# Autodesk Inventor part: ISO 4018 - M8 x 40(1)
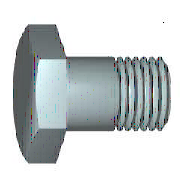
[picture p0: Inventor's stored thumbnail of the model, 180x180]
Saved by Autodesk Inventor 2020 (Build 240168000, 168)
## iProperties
Created: 2019-01
Part Number: ISO 4018 - M8 x 40(1)
Material: Ocel
Description: Šrouby se šestihrannou hlavou se závitem k hlavě. Výrobní třída C
Document SubType Name: Modeling
Standard: ISO 4018
Designer: doma
Standard Revision: Fourth edition 2011-04-01
Standards Organization: ISO
Language: cs-CZ
Size Designation: M8 x 40
Categories: <MemberInstance><Categories><Category DisplayName="Spojovací materiál" InternalName="e4da775c-781d-43d5-af7c-5136215cf5a6" Mnemonic="FSTN"><Category DisplayName
Density: 7.85 g/cm^3
Appearance: Plech
IsCustomPart: 0
Author: doma
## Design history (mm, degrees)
node "WorkPlane1"
node "WorkPoint1"
node "MSC_A1"
node "MSC_PF1"
node "MSC_PT1"
body "Solid1"
node "Náčrt1"
sketch "Náčrt2"
  geometry: L1 (-6.5, 3.753)-(-6.5, -3.753); L2 (0, 7.505)-(-6.5, 3.753); L3 (6.5, 3.753)-(0, 7.505); L4 (6.5, -3.753)-(6.5, 3.753); L5 (0, -7.505)-(6.5, -3.753); L6 (-6.5, -3.753)-(0, -7.505); C1 r 6.5 at (0, 0); 1 further point
  constraints: 12 end point, 6 tangent, 2 parallel, 2 vertical, 1 centre point
  dimensions: "d1" = 13 diameter of C1 (= ParS); "d29" = 0 distance of point (0, 0) C1.centre; "d30" = 0 distance of C1.centre point (0, 0)
extrude "Vysunutí1" new body sketch "Náčrt2" distance "d6" = 5.3 (= ParK); taper "d7" = 0 deg
revolve "Rotace1" stored, may be unused: angle "d14" = 360 deg
revolve "Rotace2" stored, may be unused: angle "d21" = 360 deg
chamfer "Zkosení1" distance "d22" = 0.625 (= 0.5 x PTC); stored, may be unused: second distance "d23" = 0.625 (= 0.5 x PTC), angle "d39" = 45 deg
fillet "Zaoblení1" dims "d24" = 0.4 (= r)
feature "Závit1" dims "d32" = 0, "b" = 37.5 (= NLG - 2 x PTC)
sketch "Náčrt3"
  geometry: L1 (6.5, 5.3)-(7.605, 5.3); L2 (7.605, 4.662)-(6.5, 5.3); L3 (7.605, 5.3)-(7.605, 4.662); L4 (0, -1.06)-(0, 6.36) reference; L5 (7.505, 0)-(7.505, 5.3) reference
  constraints: 6 end point, 1 horizontal, 1 vertical
  dimensions: "d25" = 0.1 distance between parallel lines of L5 L3; "d26" = 0 distance from line of L5.end L1; "d27" = 60 deg angle of L3 L2; "d28" = 6.5 distance from line of L4 L1.start (= 0.5 x ParS)
sketch "Náčrt4"
  geometry: L1 (0, -40)-(0, 0); L2 (-4, -40)-(0, -40); L3 (-4, 0)-(-4, -40); L4 (0, 0)-(-4, 0); L5 (0, -40)-(0, 0); L6 (-4.8, 0)-(0.8, 0) reference; L7 (0, -48)-(0, 8) reference
  constraints: 10 end point, 2 horizontal, 2 vertical
  dimensions: "d18" = 4 distance of L1.start L2.start (= 0.5 x NND); "d20" = 40 distance of L3.start L2.start (= NLG); "d33" = 0 distance between parallel lines of L7 L1; "d34" = 0 distance between parallel lines of L6 L4
other parameters: "NND" = 8 [user parameter; used in 2 equation terms], "NLG" = 40 [user parameter; used in 2 equation terms], "PTC" = 1.25 [user parameter; used in 3 equation terms], "ParK" = 5.3 [user parameter; used in 1 equation term], "ParS" = 13 [user parameter; used in 3 equation terms], "msp_es" = 7.50577 (= 0.577367 x ParS) [user parameter], "r" = 0.4 [user parameter; used in 1 equation term], "d2" = 15 (derived), "d4" = 17.32102 (derived), "d8" = 15 (derived), "d10" = 0 (derived), "d12" = 30 deg (derived), "d15" = 0 (derived), "d37" = 0, "d38" = 0, "d40" = 0, "d41" = 0, "d42" = 0, "THREADDIA" = 8 (= NND) [user parameter]
